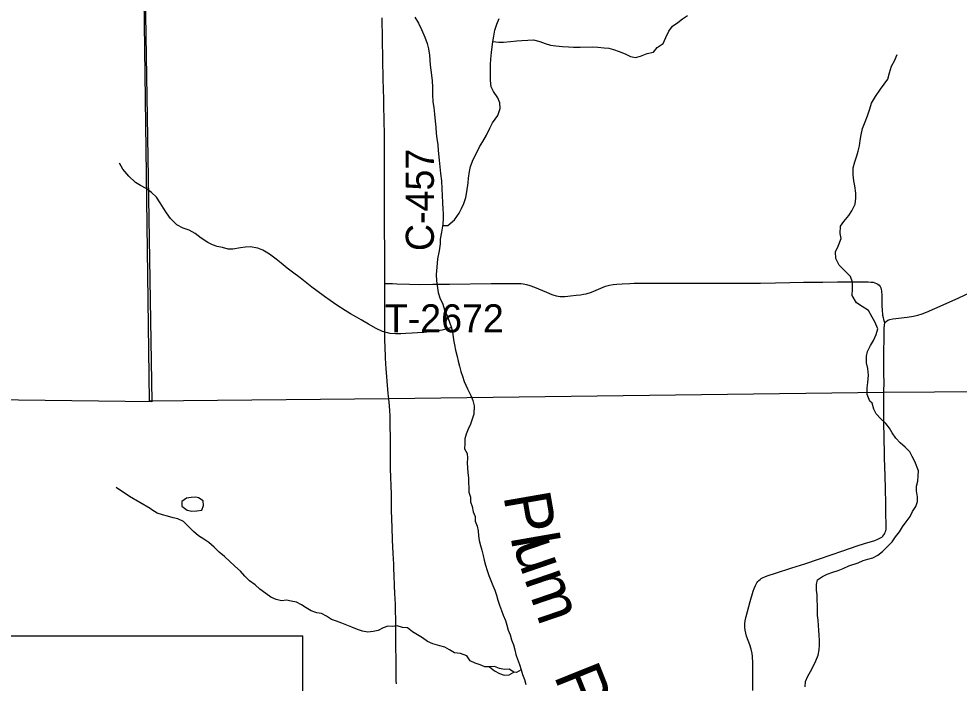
# Model space of a CAD drawing. Extents: x 0 to 34, y 0 to 22.
# Drawn here: x 3.831 to 5.733, y 18.172 to 19.516 of the extents above; entities that cross this region are included whole.
import ezdxf

# ---------------------------------------------------------------- set-up
doc = ezdxf.new("R2010")
doc.units = 0
for name, color, linetype in [('GM_X_County_Road_Text', 7, 'Continuous'), ('GM_X_Interchange_Ramps', 7, 'Continuous'), ('GM_X_Minor_River_Text', 7, 'Continuous'), ('GM_X_Section_Text', 7, 'Continuous'), ('GM_X_State_Route', 7, 'Continuous'), ('GM_X_Township_Road', 7, 'Continuous'), ('GM_X_Township_Road_Text', 7, 'Continuous'), ('GM_X_Township_Text', 7, 'Continuous'), ('SH_Text', 7, 'Continuous')]:
    doc.layers.add(name, color=color, linetype=linetype)

msp = doc.modelspace()

# ---------------------------------------------------------------- linework, layer by layer
at = {"layer": 'GM_X_County_Road_Text'}
for points in [[(4.632, 19.5192), (4.6396, 19.5071), (4.6457, 19.4946), (4.6523, 19.479), (4.6569, 19.4662), (4.6596, 19.4555), (4.6615, 19.4426), (4.6631, 19.4225), (4.6643, 19.4123), (4.6658, 19.4024), (4.667, 19.3907), (4.6678, 19.3778), (4.6679, 19.363), (4.6687, 19.3482), (4.6703, 19.3368), (4.6719, 19.3235), (4.6731, 19.3087), (4.6742, 19.2966), (4.6754, 19.2841), (4.6766, 19.2738), (4.6782, 19.2609), (4.6794, 19.2499), (4.6813, 19.2302), (4.6829, 19.2165), (4.6841, 19.2033), (4.6857, 19.1885), (4.6869, 19.1722), (4.6873, 19.1585), (4.6882, 19.1441), (4.6886, 19.1308), (4.689, 19.1213), (4.689, 19.1118), (4.6883, 19.1008), (4.6858, 19.0845), (4.6835, 19.0704), (4.6832, 19.0606), (4.681, 19.0469), (4.678, 19.0302), (4.6762, 19.0135), (4.6751, 18.9991), (4.6759, 18.9862), (4.6771, 18.9767), (4.6794, 18.9623), (4.6829, 18.9517), (4.6886, 18.9388), (4.6921, 18.927), (4.6971, 18.9153), (4.7024, 18.9024), (4.7063, 18.8907), (4.7086, 18.8778), (4.7105, 18.8668), (4.7121, 18.8565), (4.7144, 18.8459), (4.7175, 18.8326), (4.7194, 18.8232), (4.7221, 18.8133), (4.7252, 18.8027), (4.7283, 18.7928), (4.7321, 18.7822), (4.7382, 18.7678), (4.7451, 18.7538), (4.749, 18.744), (4.7517, 18.7332)], [(4.6879, 19.0978), (4.6986, 19.0982), (4.7122, 19.1093), (4.7216, 19.1226), (4.7265, 19.1325), (4.731, 19.1427), (4.7351, 19.1549), (4.7369, 19.1659), (4.7399, 19.1841), (4.7406, 19.1936), (4.7425, 19.2073), (4.7447, 19.2172), (4.7499, 19.2312), (4.7552, 19.2419), (4.7631, 19.2571), (4.7695, 19.2677), (4.777, 19.281), (4.7834, 19.2947), (4.7894, 19.3058), (4.7996, 19.3202), (4.8045, 19.3343), (4.8037, 19.346), (4.8002, 19.3563), (4.7914, 19.3688), (4.7865, 19.3786), (4.7853, 19.3911), (4.7852, 19.4014), (4.7848, 19.4109), (4.7848, 19.4238), (4.7855, 19.4344), (4.7869, 19.4477), (4.7884, 19.4591), (4.7895, 19.4693), (4.7917, 19.4811), (4.7939, 19.4932), (4.7981, 19.505), (4.8026, 19.5164)], [(4.7897, 19.4703), (4.8016, 19.4686), (4.8115, 19.469), (4.8255, 19.4702), (4.838, 19.4714), (4.8486, 19.4722), (4.8603, 19.473), (4.8721, 19.4734), (4.8846, 19.4704), (4.8956, 19.4659), (4.9062, 19.4629), (4.9172, 19.4611), (4.9305, 19.46), (4.9426, 19.4593), (4.9529, 19.4589), (4.9661, 19.459), (4.9915, 19.4591), (5.0018, 19.4587), (5.0147, 19.4576), (5.0241, 19.4565), (5.034, 19.4543), (5.0454, 19.4502), (5.0572, 19.4449), (5.0682, 19.4396), (5.078, 19.4381), (5.0886, 19.4405), (5.1022, 19.4462), (5.1144, 19.4485), (5.1219, 19.458), (5.134, 19.4661), (5.1396, 19.4782), (5.1456, 19.4911), (5.1532, 19.5014), (5.1638, 19.5087), (5.1736, 19.5159), (5.1834, 19.5228)], [(5.5566, 18.7387), (5.552, 18.7428), (5.5467, 18.7561), (5.547, 18.7693), (5.5484, 18.7804), (5.5495, 18.7952), (5.548, 18.8084), (5.5456, 18.8202), (5.5456, 18.8335), (5.5478, 18.843), (5.5538, 18.8551), (5.5598, 18.8654), (5.5647, 18.8772), (5.5685, 18.8886), (5.5623, 18.903), (5.557, 18.9128), (5.5494, 18.9257), (5.5364, 18.934), (5.525, 18.9412), (5.5163, 18.9563), (5.5173, 18.9696), (5.5169, 18.9836), (5.5131, 18.995), (5.4902, 19.0177), (5.4833, 19.0313), (5.4825, 19.0446), (5.4885, 19.0564), (5.4942, 19.0716), (5.4922, 19.0815), (5.4929, 19.0963), (5.4993, 19.1062), (5.5095, 19.118), (5.5155, 19.1278), (5.5223, 19.1408), (5.5241, 19.1533), (5.5237, 19.1636), (5.5218, 19.178), (5.5198, 19.1886), (5.5186, 19.2007), (5.5186, 19.2148), (5.5216, 19.2265), (5.5261, 19.2391), (5.5283, 19.2486), (5.5313, 19.2592), (5.5327, 19.2698), (5.5346, 19.2816), (5.5372, 19.2941), (5.5428, 19.3078), (5.5477, 19.32), (5.5522, 19.3341), (5.5559, 19.3454), (5.5635, 19.3588), (5.574, 19.3736), (5.5883, 19.3941), (5.5917, 19.4071), (5.5958, 19.42), (5.6018, 19.4314), (5.6074, 19.4436)], [(4.706, 18.8916), (4.6979, 18.8891), (4.6873, 18.8864), (4.6752, 18.8845), (4.6627, 18.8825), (4.6502, 18.8813), (4.6377, 18.8805), (4.6267, 18.8801), (4.6135, 18.8793), (4.604, 18.8789), (4.5926, 18.8785), (4.582, 18.8796), (4.5668, 18.8837), (4.5539, 18.8893), (4.538, 18.8984), (4.5235, 18.907), (4.5137, 18.9127), (4.5019, 18.9195), (4.4909, 18.9263), (4.4745, 18.9365), (4.4608, 18.9459), (4.4494, 18.9542), (4.4339, 18.9659), (4.424, 18.9731), (4.4137, 18.981), (4.4, 18.992), (4.3844, 19.0037), (4.3738, 19.0116), (4.362, 19.0214), (4.3517, 19.0297), (4.3384, 19.0399), (4.3244, 19.0478), (4.3145, 19.052), (4.2993, 19.0546), (4.2895, 19.0542), (4.2796, 19.0526), (4.2641, 19.0503), (4.2546, 19.0502), (4.2429, 19.0532), (4.2322, 19.0555), (4.2228, 19.0585), (4.2133, 19.0634), (4.1996, 19.072), (4.1878, 19.0815), (4.1756, 19.0883), (4.1635, 19.0924), (4.151, 19.0992), (4.1376, 19.112), (4.13, 19.1234), (4.1235, 19.1332), (4.1167, 19.1438), (4.1094, 19.1552), (4.0991, 19.165), (4.0885, 19.1726), (4.0775, 19.1786), (4.0672, 19.185), (4.0535, 19.1979), (4.0413, 19.2122), (4.0345, 19.224)], [(5.6041, 18.4678), (5.6125, 18.4783), (5.6186, 18.4885), (5.6259, 18.4983), (5.6336, 18.5092), (5.6382, 18.5194), (5.6455, 18.5296), (5.6486, 18.5395), (5.6483, 18.5493), (5.6465, 18.5611), (5.6466, 18.5709), (5.649, 18.5808), (5.6498, 18.5918), (5.6503, 18.6016), (5.6429, 18.6207), (5.638, 18.6306), (5.6328, 18.6401), (5.6234, 18.6497), (5.6136, 18.6581), (5.6046, 18.6676), (5.5971, 18.6783), (5.5919, 18.6879), (5.5844, 18.6974), (5.5746, 18.7066), (5.5652, 18.7169), (5.56, 18.7265), (5.5566, 18.7387)], [(4.7517, 18.7332), (4.7514, 18.7163), (4.7479, 18.7061), (4.7448, 18.6963), (4.7398, 18.6861), (4.7359, 18.6759), (4.7332, 18.6661), (4.7331, 18.6566), (4.7326, 18.6463), (4.7379, 18.6368), (4.7385, 18.6273), (4.7381, 18.6179), (4.7384, 18.6076), (4.739, 18.5977), (4.7405, 18.5875), (4.7408, 18.5776), (4.7414, 18.5678), (4.7414, 18.5583), (4.7443, 18.5484), (4.7446, 18.5389), (4.748, 18.5294), (4.7498, 18.5188), (4.7542, 18.5092), (4.7538, 18.4998), (4.7579, 18.4899), (4.7601, 18.48), (4.7607, 18.4701), (4.7622, 18.4606), (4.7647, 18.4508), (4.7677, 18.4409), (4.7699, 18.4302), (4.7721, 18.4207), (4.7746, 18.4105), (4.7783, 18.3998), (4.7817, 18.3899), (4.7854, 18.38), (4.7895, 18.3698), (4.7939, 18.3602), (4.7973, 18.3503), (4.8002, 18.3401), (4.8035, 18.3298), (4.8076, 18.3192), (4.8109, 18.3093), (4.8154, 18.299), (4.8184, 18.2895), (4.8206, 18.2796), (4.825, 18.2701), (4.8276, 18.2598), (4.8317, 18.2499), (4.8342, 18.2393), (4.8364, 18.2298), (4.8398, 18.2203), (4.8435, 18.21), (4.8468, 18.199), (4.8498, 18.1895), (4.8535, 18.1796), (4.8568, 18.1693)], [(4.0967, 18.5251), (4.0552, 18.5497), (4.0277, 18.5681)], [(4.7832, 18.2052), (4.7737, 18.2053), (4.7639, 18.2092), (4.754, 18.2123), (4.7439, 18.2173), (4.7371, 18.2273), (4.7246, 18.2319), (4.7125, 18.2332), (4.7023, 18.2393), (4.6925, 18.2447), (4.6823, 18.2479), (4.6687, 18.2518), (4.6578, 18.2564), (4.6472, 18.2637), (4.6374, 18.2699), (4.6276, 18.2757), (4.617, 18.2837), (4.6068, 18.2849), (4.5962, 18.2877), (4.5868, 18.287), (4.5773, 18.2871), (4.5678, 18.2838), (4.5579, 18.2789), (4.548, 18.2764), (4.537, 18.2753), (4.5264, 18.277), (4.5162, 18.2805), (4.5049, 18.2851), (4.4845, 18.2936), (4.4739, 18.2975), (4.4637, 18.301), (4.4535, 18.3076), (4.4433, 18.313), (4.4335, 18.3146), (4.4221, 18.3185), (4.4123, 18.3246), (4.4025, 18.3304), (4.3927, 18.3358), (4.3821, 18.3378), (4.3723, 18.3398), (4.3624, 18.3387), (4.3518, 18.3411), (4.3409, 18.3457), (4.3307, 18.3534), (4.3186, 18.3619), (4.3089, 18.3707), (4.2979, 18.3791), (4.2882, 18.3887), (4.2795, 18.3983), (4.2679, 18.4086), (4.2468, 18.4285), (4.2363, 18.4373), (4.2265, 18.4469), (4.2152, 18.4569), (4.2054, 18.4634), (4.1948, 18.4703), (4.1847, 18.4787), (4.1745, 18.4891), (4.164, 18.499), (4.153, 18.5048), (4.1432, 18.5064), (4.1319, 18.5099), (4.1216, 18.5123), (4.1107, 18.5162), (4.1001, 18.5227), (4.0967, 18.5251)], [(5.4211, 18.1649), (5.422, 18.1756), (5.4266, 18.1861), (5.4324, 18.1959), (5.4382, 18.2069), (5.4432, 18.2171), (5.4474, 18.2284), (5.4498, 18.2394), (5.4503, 18.2489), (5.4503, 18.2583), (5.4497, 18.2694), (5.4494, 18.2792), (5.4487, 18.2887), (5.448, 18.2993), (5.4466, 18.3088), (5.4467, 18.3191), (5.4464, 18.3289), (5.4457, 18.3399), (5.4458, 18.3509), (5.4444, 18.3604), (5.4445, 18.3714), (5.4464, 18.3813), (5.4563, 18.3876), (5.4662, 18.3924), (5.4773, 18.3969), (5.4879, 18.4002), (5.4985, 18.4043), (5.5096, 18.4091), (5.5286, 18.4158), (5.5385, 18.4199), (5.548, 18.4232), (5.5582, 18.4257), (5.5681, 18.4313), (5.578, 18.4381), (5.588, 18.4486), (5.5975, 18.458), (5.6041, 18.4678)], [(4.8468, 18.199), (4.8373, 18.1937), (4.8324, 18.1945)]]:
    msp.add_lwpolyline(points, dxfattribs=at)
at = {"layer": 'GM_X_Interchange_Ramps'}
for points in [[(4.5711, 18.9806), (4.5783, 18.9805), (4.5867, 18.9803), (4.5954, 18.98), (4.6211, 18.9793), (4.6423, 18.9785), (4.6681, 18.9791), (4.7023, 18.9795), (4.7862, 18.9805), (4.8017, 18.9807), (4.8203, 18.9806), (4.8429, 18.9809), (4.8473, 18.9804), (4.8512, 18.9798), (4.8577, 18.9784), (4.8645, 18.9765), (4.8738, 18.9734), (4.898, 18.9628), (4.9089, 18.9581), (4.9179, 18.9558), (4.9257, 18.9546), (4.9357, 18.9545), (4.9415, 18.955), (4.947, 18.9556), (4.958, 18.9567), (4.9671, 18.9578), (4.973, 18.9587), (4.9786, 18.96), (4.9893, 18.9631), (5.0085, 18.9713), (5.0178, 18.9749), (5.0257, 18.977), (5.0331, 18.9785), (5.0406, 18.9795), (5.051, 18.9802), (5.0665, 18.9808), (5.0758, 18.9811), (5.0912, 18.9812), (5.1253, 18.9813), (5.1656, 18.9814), (5.178, 18.9816), (5.2241, 18.9811), (5.2454, 18.9811), (5.2832, 18.981), (5.3308, 18.9815), (5.3616, 18.9821), (5.3903, 18.9827), (5.4181, 18.9831), (5.4569, 18.9835), (5.4866, 18.9838), (5.506, 18.9838), (5.522, 18.984), (5.5373, 18.9843), (5.5491, 18.9841), (5.5547, 18.9836), (5.5587, 18.9831), (5.5622, 18.9819), (5.5654, 18.9808), (5.5683, 18.9791), (5.5712, 18.9772), (5.5729, 18.9747), (5.5743, 18.9721), (5.5753, 18.9686), (5.5759, 18.9659), (5.5761, 18.9626), (5.5762, 18.9594), (5.5764, 18.947), (5.5768, 18.935), (5.577, 18.9276), (5.578, 18.9165), (5.5789, 18.9117), (5.5799, 18.9079), (5.5811, 18.9039), (5.5825, 18.9004)], [(5.5825, 18.9004), (5.5838, 18.9022), (5.5851, 18.9039), (5.5885, 18.9063), (5.5925, 18.9079), (5.5988, 18.9092), (5.6277, 18.9127), (5.6403, 18.9145), (5.6496, 18.9164), (5.6582, 18.9192), (5.6671, 18.9226), (5.684, 18.9299), (5.7068, 18.9404), (5.7319, 18.9515), (5.755, 18.9622)], [(5.5806, 18.7599), (5.5812, 18.7821), (5.5808, 18.7952), (5.5808, 18.8089), (5.5807, 18.8401), (5.5809, 18.8711), (5.5813, 18.8913), (5.5816, 18.8952), (5.582, 18.8977), (5.5825, 18.9004)], [(5.3153, 18.1573), (5.3156, 18.176), (5.3157, 18.2008), (5.3155, 18.2132), (5.3148, 18.2257), (5.314, 18.2318), (5.312, 18.2409), (5.3093, 18.2498), (5.3029, 18.2674), (5.3011, 18.2733), (5.2999, 18.2794), (5.2992, 18.2856), (5.2993, 18.2918), (5.3001, 18.298), (5.3021, 18.3071), (5.3103, 18.3371), (5.3163, 18.358), (5.3183, 18.3639), (5.3207, 18.3697), (5.3221, 18.3724), (5.3238, 18.375), (5.3256, 18.3775), (5.3277, 18.3798), (5.3301, 18.3818), (5.3327, 18.3838), (5.3353, 18.3852), (5.3409, 18.3877), (5.3468, 18.3898), (5.3617, 18.3944), (5.3942, 18.4051), (5.4208, 18.4138), (5.4502, 18.4237), (5.4973, 18.4399), (5.5268, 18.4496), (5.5417, 18.4543), (5.5624, 18.4609), (5.5682, 18.4631), (5.5711, 18.4644), (5.5738, 18.4659), (5.5764, 18.4677), (5.5787, 18.4697), (5.5807, 18.472), (5.5823, 18.4747), (5.5835, 18.4775), (5.5844, 18.4804), (5.585, 18.4835), (5.5853, 18.4866), (5.5855, 18.4928), (5.5849, 18.5146), (5.5843, 18.5363), (5.5841, 18.5643), (5.5832, 18.5922), (5.5828, 18.6088), (5.5822, 18.6284), (5.5818, 18.6435), (5.5813, 18.6613), (5.581, 18.6738), (5.5805, 18.6947), (5.5805, 18.7221), (5.5805, 18.7419), (5.5806, 18.7599)], [(4.5951, 18.171), (4.5945, 18.1771), (4.5942, 18.1955), (4.594, 18.2203), (4.5938, 18.2451), (4.5937, 18.2572), (4.5937, 18.2711), (4.5936, 18.2784), (4.5936, 18.2876), (4.5928, 18.332), (4.5918, 18.3537), (4.591, 18.3692), (4.5902, 18.3908), (4.5897, 18.4032), (4.5892, 18.4125), (4.5882, 18.4342), (4.5871, 18.4622), (4.5862, 18.487), (4.5851, 18.5211), (4.5845, 18.5553), (4.5841, 18.5708), (4.5835, 18.5895), (4.5829, 18.605), (4.5825, 18.6205), (4.5827, 18.6329), (4.5831, 18.6515), (4.583, 18.6577), (4.5829, 18.667), (4.5824, 18.695), (4.5819, 18.7137), (4.5814, 18.7228), (4.5806, 18.7328), (4.5793, 18.7473)]]:
    msp.add_lwpolyline(points, dxfattribs=at)
at = {"layer": 'GM_X_Minor_River_Text'}
for points in [[(4.1894, 18.5485), (4.1799, 18.5478), (4.1704, 18.546), (4.1609, 18.5396), (4.1608, 18.5302), (4.1714, 18.5221), (4.1812, 18.5197), (4.1911, 18.5204), (4.2009, 18.5222), (4.2044, 18.5317)], [(4.2044, 18.5317), (4.2041, 18.5411), (4.1943, 18.5473), (4.1894, 18.5485)], [(4.8032, 18.202), (4.793, 18.2055), (4.7832, 18.2052), (4.793, 18.1972), (4.8035, 18.1918), (4.8126, 18.1883)], [(4.8126, 18.1883), (4.8225, 18.189), (4.8324, 18.1945), (4.8226, 18.2003), (4.8131, 18.1997), (4.8032, 18.202)]]:
    msp.add_lwpolyline(points, dxfattribs=at)
at = {"layer": 'GM_X_State_Route'}
for points in [[(8.6602, 18.8038), (8.6602, 21.1866), (4.0708, 21.1866), (4.0805, 19.8173), (4.0805, 19.8117), (4.0945, 18.7432), (4.5791, 18.7479), (5.5804, 18.7605), (5.5812, 18.7605), (6.0902, 18.7638), (7.082, 18.7532), (7.9519, 18.7787), (8.0539, 18.7796), (8.5878, 18.803)], [(3.0705, 19.7579), (4.0835, 19.7451), (4.0839, 19.7307), (4.0999, 18.7413), (3.0743, 18.754)]]:
    msp.add_lwpolyline(points, close=True, dxfattribs=at)
at = {"layer": 'GM_X_Township_Road'}
for points in [[(4.5711, 18.9806), (4.5711, 18.9905), (4.5711, 18.9998), (4.5711, 19.0214), (4.5711, 19.0276), (4.571, 19.0462), (4.5708, 19.0928), (4.5708, 19.1332), (4.5709, 19.1705), (4.5708, 19.2015), (4.5707, 19.2202), (4.5706, 19.248), (4.5705, 19.276), (4.5699, 19.3163), (4.5695, 19.335), (4.5691, 19.3536), (4.5682, 19.3939), (4.5668, 19.4747), (4.566, 19.5182)], [(4.5793, 18.7473), (4.5782, 18.7582), (4.5759, 18.7829), (4.5751, 18.7922), (4.5741, 18.8077), (4.5729, 18.8294), (4.5718, 18.8542), (4.5715, 18.8634), (4.5714, 18.8696), (4.5712, 18.882), (4.5711, 18.9006), (4.5711, 18.913), (4.5711, 18.9254), (4.5711, 18.9502), (4.5711, 18.975), (4.5711, 18.9806)]]:
    msp.add_lwpolyline(points, dxfattribs=at)
at = {"layer": 'SH_Text'}
for p in [(2.0719, 18.2679), (4.4056, 17.4855)]:
    msp.add_line(p, (4.4056, 18.2679), dxfattribs=at)

# ---------------------------------------------------------------- texts
at = {"layer": 'GM_X_Section_Text'}
msp.add_text('C-457', height=0.05682, rotation=90, dxfattribs=at).set_placement((4.6705, 19.0462))
at = {"layer": 'GM_X_Township_Road_Text'}
for s, rotation, p in [('Pl', 279.8812, (4.8109, 18.5514)), ('um', 288.8809, (4.8298, 18.4516)), ('Run', 291.8808, (4.9124, 18.1875))]:
    msp.add_text(s, height=0.09472, rotation=rotation, dxfattribs=at).set_placement(p)
at = {"layer": 'GM_X_Township_Text'}
msp.add_text('T-2672', height=0.05682, rotation=359.9991, dxfattribs=at).set_placement((4.5712, 18.8817))

doc.saveas('drawing.dxf')
